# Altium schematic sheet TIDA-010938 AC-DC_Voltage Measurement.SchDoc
size 431 x 279 mm; Date: Not shown in title block; ApprovedBy: Not shown in title block; CheckedBy: Not shown in title block; Author: Not shown in title block; CompanyName: Not shown in title block; Engineer: Not shown in title block; Organization: Not shown in title block; Address1: Not shown in title block; Address2: Not shown in title block; Address3: Not shown in title block; Address4: Not shown in title block; DocumentNumber: 6; Revision: Use project parameter SCH_Rev; SheetNumber: 7; SheetTotal: 11; PageSetup: Record=PageOptions¦CenterHorizontal=True¦CenterVertical=True¦PrintScale=1.00¦XCorrection=1.00¦YCorrection=1.00¦PrintKind=0¦BorderSize=5000000¦LeftOffset=0¦BottomOffset=0¦Orientation=2¦PaperLength=1000¦PaperWidth=1000¦Scale=100¦PaperSource=15¦PrintQuality=600¦MediaType=1¦DitherType=10¦PaperKind=Letter¦PrintScaleMode=1
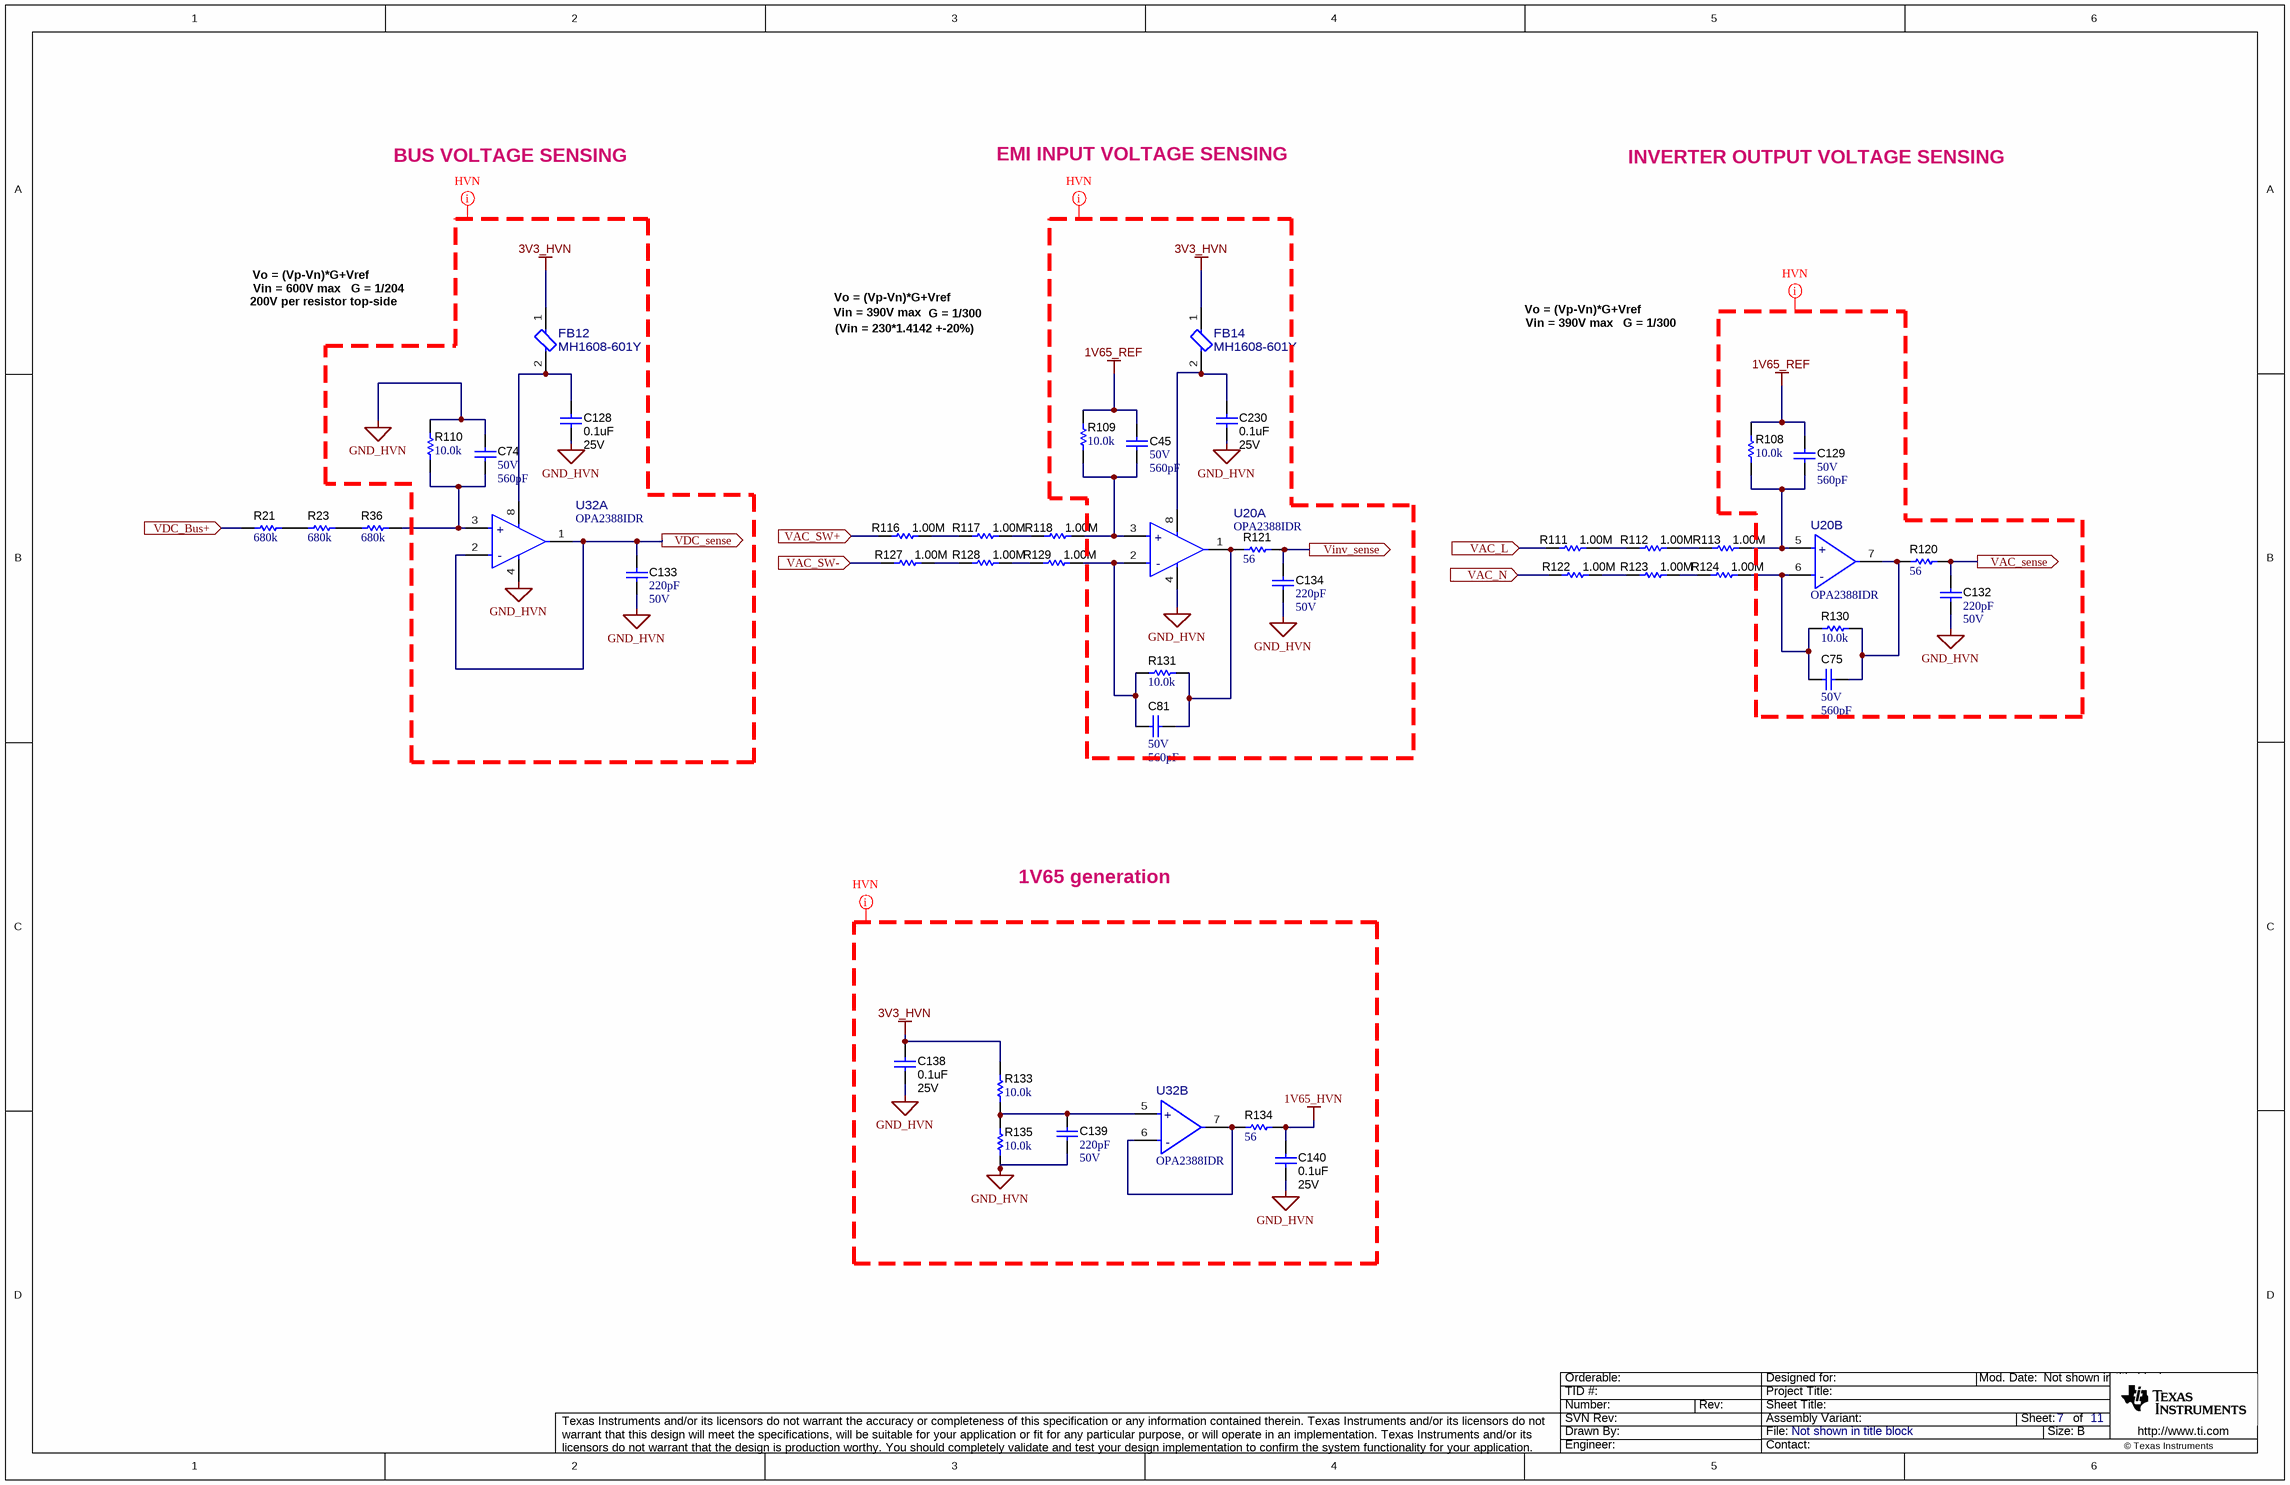
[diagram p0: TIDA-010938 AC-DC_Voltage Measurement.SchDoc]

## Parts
C45  VDC_V: 50V  ValueDisplayed: 560pF  [0603]  (hidden comment: GRM1885C1H561JA01D)
C74  VDC_V: 50V  ValueDisplayed: 560pF  [0603]  (hidden comment: GRM1885C1H561JA01D)
C75  VDC_V: 50V  ValueDisplayed: 560pF  [0603]  (hidden comment: GRM1885C1H561JA01D)
C81  VDC_V: 50V  ValueDisplayed: 560pF  [0603]  (hidden comment: GRM1885C1H561JA01D)
C128  ValueDisplayed: 0.1uF  VDC_V: 25V  [0603]  (hidden comment: C0603X104K3RACTU)
C129  VDC_V: 50V  ValueDisplayed: 560pF  [0603]  (hidden comment: GRM1885C1H561JA01D)
C132  Cap_F: 220pF  VDC_V: 50V  [0603]  (hidden comment: GRM188R71H221KA01D)
C133  Cap_F: 220pF  VDC_V: 50V  [0603]  (hidden comment: GRM188R71H221KA01D)
C134  Cap_F: 220pF  VDC_V: 50V  [0603]  (hidden comment: GRM188R71H221KA01D)
C138  ValueDisplayed: 0.1uF  VDC_V: 25V  [0603]  (hidden comment: C0603X104K3RACTU)
C139  Cap_F: 220pF  VDC_V: 50V  [0603]  (hidden comment: GRM188R71H221KA01D)
C140  ValueDisplayed: 0.1uF  VDC_V: 25V  [0603]  (hidden comment: C0603X104K3RACTU)
C230  ValueDisplayed: 0.1uF  VDC_V: 25V  [0603]  (hidden comment: C0603X104K3RACTU)
FB12  MH1608-601Y  [FP-MH1608-601Y_0603-MFG]
FB14  MH1608-601Y  [FP-MH1608-601Y_0603-MFG]
R21  ValueDisplayed: 680k  [TNPV1206]  (hidden comment: TNPV1206680KBEEN)
R23  ValueDisplayed: 680k  [TNPV1206]  (hidden comment: TNPV1206680KBEEN)
R36  ValueDisplayed: 680k  [TNPV1206]  (hidden comment: TNPV1206680KBEEN)
R108  ValueDisplayed: 10.0k  [0603]  (hidden comment: RG1608P-103-B-T5)
R109  ValueDisplayed: 10.0k  [0603]  (hidden comment: RG1608P-103-B-T5)
R110  ValueDisplayed: 10.0k  [0603]  (hidden comment: RG1608P-103-B-T5)
R111  ValueDisplayed: 1.00M  [TNPV1206]  (hidden comment: TNPV12061M00BEEN)
R112  ValueDisplayed: 1.00M  [TNPV1206]  (hidden comment: TNPV12061M00BEEN)
R113  ValueDisplayed: 1.00M  [TNPV1206]  (hidden comment: TNPV12061M00BEEN)
R116  ValueDisplayed: 1.00M  [TNPV1206]  (hidden comment: TNPV12061M00BEEN)
R117  ValueDisplayed: 1.00M  [TNPV1206]  (hidden comment: TNPV12061M00BEEN)
R118  ValueDisplayed: 1.00M  [TNPV1206]  (hidden comment: TNPV12061M00BEEN)
R120  ValueDisplayed: 56  [0603]  (hidden comment: RG1608P-560-B-T5)
R121  ValueDisplayed: 56  [0603]  (hidden comment: RG1608P-560-B-T5)
R122  ValueDisplayed: 1.00M  [TNPV1206]  (hidden comment: TNPV12061M00BEEN)
R123  ValueDisplayed: 1.00M  [TNPV1206]  (hidden comment: TNPV12061M00BEEN)
R124  ValueDisplayed: 1.00M  [TNPV1206]  (hidden comment: TNPV12061M00BEEN)
R127  ValueDisplayed: 1.00M  [TNPV1206]  (hidden comment: TNPV12061M00BEEN)
R128  ValueDisplayed: 1.00M  [TNPV1206]  (hidden comment: TNPV12061M00BEEN)
R129  ValueDisplayed: 1.00M  [TNPV1206]  (hidden comment: TNPV12061M00BEEN)
R130  ValueDisplayed: 10.0k  [0603]  (hidden comment: RG1608P-103-B-T5)
R131  ValueDisplayed: 10.0k  [0603]  (hidden comment: RG1608P-103-B-T5)
R133  ValueDisplayed: 10.0k  [0603]  (hidden comment: RG1608P-103-B-T5)
R134  ValueDisplayed: 56  [0603]  (hidden comment: RG1608P-560-B-T5)
R135  ValueDisplayed: 10.0k  [0603]  (hidden comment: RG1608P-103-B-T5)
U20  OPA2388IDR  [D0008A-MFG]  (parts A,B of 2)
U32  OPA2388IDR  [D0008A-MFG]  (parts A,B of 2)

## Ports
VAC_L (in), VAC_N (in), VAC_sense (out), VAC_SW+ (in), VAC_SW- (in), VDC_Bus+ (in), VDC_sense (out), Vinv_sense (out)

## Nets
1V65_HVN: C140.2 R134.2
1V65_REF: C45.2 C129.2 R108.2 R109.2
3V3_HVN: C138.2 FB12.1 FB14.1 R133.1
GND_HVN: C74.1 C128.1 C132.1 C133.1 C134.1 C138.1 C139.1 C140.1 C230.1 R110.2 R135.2 U20.4(V-) U32.4(V-)
VAC_L: R111.1 ; port VAC_L
VAC_N: R122.1 ; port VAC_N
VAC_sense: C132.2 R120.2 ; port VAC_sense
VAC_SW+: R116.1 ; port VAC_SW+
VAC_SW-: R127.1 ; port VAC_SW-
VDC_Bus+: R21.1 ; port VDC_Bus+
VDC_sense: C133.2 U32.1(OUT_A) U32.2(-IN_A) ; port VDC_sense
Vinv_sense: C134.2 R121.2 ; port Vinv_sense
NetC45_1: C45.1 R109.1 R118.2 U20.3(+IN_A)
NetC74_2: C74.2 R36.2 R110.1 U32.3(+IN_A)
NetC75_1: C75.1 R124.2 R130.2 U20.6(-IN_B)
NetC75_2: C75.2 R120.1 R130.1 U20.7(OUT_B)
NetC81_1: C81.1 R129.2 R131.2 U20.2(-IN_A)
NetC81_2: C81.2 R121.1 R131.1 U20.1(OUT_A)
NetC128_2: C128.2 FB12.2 U32.8(V+)
NetC129_1: C129.1 R108.1 R113.2 U20.5(+IN_B)
NetC139_2: C139.2 R133.2 R135.1 U32.5(+IN_B)
NetC230_2: C230.2 FB14.2 U20.8(V+)
NetR21_2: R21.2 R23.1
NetR23_2: R23.2 R36.1
NetR111_2: R111.2 R112.1
NetR112_2: R112.2 R113.1
NetR116_2: R116.2 R117.1
NetR117_2: R117.2 R118.1
NetR122_2: R122.2 R123.1
NetR123_2: R123.2 R124.1
NetR127_2: R127.2 R128.1
NetR128_2: R128.2 R129.1
NetR134_1: R134.1 U32.6(-IN_B) U32.7(OUT_B)

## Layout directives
net class HVN: 1V65_HVN, 1V65_REF, 3V3_HVN, GND_HVN

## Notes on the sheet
- BUS VOLTAGE SENSING
- EMI INPUT VOLTAGE SENSING
- INVERTER OUTPUT VOLTAGE SENSING
- Vin = 600V max
- Vo = (Vp-Vn)*G+Vref
- 200V per resistor top-side
- G = 1/204
- Vin = 390V max
- (Vin = 230*1.4142 +-20%)
- G = 1/300
- 1V65 generation

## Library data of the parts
C45 C74 C75 C81 C129 = CMP-0007225-4: CAP, CERM, 560 pF, 50 V, +/- 5%, C0G/NP0, 0603; Manufacturer: MuRata; TaMin_C: -55°C; Polarized: N; SizeAreaWB_mm2: 4.68; Value1: Unknown; U/M: EA; Value: 560pF; TaMax_C: 125°C; SizeZ_mm: 1; SizeX_mm: 1.6; SizeY_mm: 0.8; SizeArea_mm2: 1.28; AEC Category: Q200
C128 C138 C140 C230 = CMP-0006979-5: CAP, CERM, 0.1 uF, 25 V, +/- 10%, X7R, 0603; Manufacturer: Kemet; Polarized: N; Value: 0.1uF; U/M: EA; Cap_F: 100nF; Value1: Unknown; TaMin_C: -55°C; TaMax_C: 125°C; AEC Category: Q200; SizeArea_mm2: 1.28; SizeAreaWB_mm2: 4.68; SizeX_mm: 1.6; SizeY_mm: 0.8; SizeZ_mm: 1
C132-C134 C139 = CMP-0007442-5: CAP, CERM, 220 pF, 50 V, +/- 10%, X7R, 0603; Manufacturer: MuRata; TaMin_C: -55°C; Polarized: N; SizeAreaWB_mm2: 4.68; Value1: Unknown; U/M: EA; Value: 220pF; TaMax_C: 125°C; SizeZ_mm: 1; SizeX_mm: 1.6; SizeY_mm: 0.8; SizeArea_mm2: 1.28; AEC Category: Q200
FB12 FB14 = CMP-0037505-1: 600 Ohms @ 100 MHz 1 Power, Signal Line Ferrite Bead 0603 (1608 Metric) 1A 200mOhm; Manufacturer: Bourns; DCR_ohm: 0.2; SizeZ_mm: 1mm; AEC Qualified: No; Impedance At Frequency: 600Ω @ 100MHz; Test Frequency: 100MHz; Tolerance_%: 25%
R21 R23 R36 = CMP-0018816-2: RES, 680 k, 0.1%, 1 W, 1206; Manufacturer: Vishay Draloric; Power_W: 1W; TempCo: 25 ppm/C; U/M: EA; Value: 680k; SizeX_mm: 3.2; SizeY_mm: 1.6; SizeZ_mm: 0.65; SizeArea_mm2: 5.12; AEC Qualified: N; VDC_V: 700V; AEC Category: Q200
R108-R110 R130 R131 R133 R135 = CMP-0023404-3: RES, 10.0 k, 0.1%, 0.1 W, 0603; Manufacturer: Susumu Co Ltd; Power_W: 100mW; TempCo: 25 ppm/C; Value_Code: 10k0; U/M: EA; Value: 10.0k; EIA_Code: E192; Res_ohm: 10k; SizeX_mm: 1.6; SizeY_mm: 0.8; SizeZ_mm: 1; Value2: 0.1W; SizeArea_mm2: 1.28; VDC_V: 75V; AEC Category: Q200
R111-R113 R116-R118 R122-R124 R127-R129 = CMP-0018805-2: RES, 1.00 M, 0.1%, 1 W, 1206; Manufacturer: Vishay Draloric; Power_W: 1W; TempCo: 25 ppm/C; Value_Code: 1M00; U/M: EA; Value: 1.00Meg; EIA_Code: E192; Res_ohm: 1M; SizeX_mm: 3.2; SizeY_mm: 1.6; SizeZ_mm: 0.65; SizeArea_mm2: 5.12; AEC Qualified: N; VDC_V: 700V; AEC Category: Q200
R120 R121 R134 = CMP-0023572-3: RES, 56, 0.1%, 0.1 W, 0603; Manufacturer: Susumu Co Ltd; Power_W: 100mW; TempCo: 25 ppm/C; Value_Code: 56R0; U/M: EA; Value: 56; SizeX_mm: 1.6; SizeY_mm: 0.8; SizeZ_mm: 1; Value2: 0.1W; SizeArea_mm2: 1.28; VDC_V: 75V; AEC Category: Q200
U20 U32 = CMP-0097119-1: Precision, Zero-Drift, Zero-Crossover, True Rail-to-Rail, Input/Output Operational Amplifiers; Manufacturer: Texas Instruments; TJmax_C: +150°C; TaMin_C: -55°C; AEC Qualified: No; Max Dual Supply Voltage: 2.75V; Min Dual Supply Voltage: 1.25V; Input Offset Voltage: 0.00025mV; Output Current Per Channel: 30-60mA; Standoff Height: 0.11mm; Number Of Channels: 2; Min Supply Voltage: 2.5V; Input Bias Current: 0.00003uA; Nominal Supply Current: 1.7-1.9mA; Voltage Gain: 126-148dB; Bandwidth: 10MHz; SizeZ_mm: 1.75mm; Max Supply Voltage: 5.5V; Response Time: 0.75-2us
